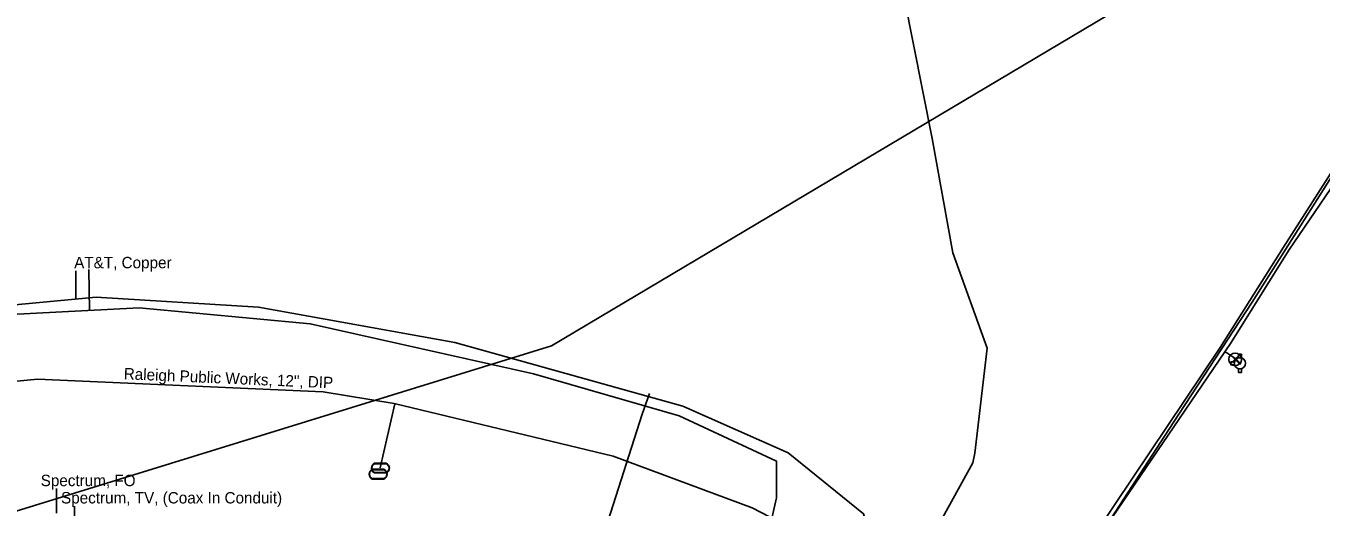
# Model space of a CAD drawing. Extents: x 2070721 to 2083340, y 729290 to 737883.
# Drawn here: x 2081646.1 to 2082100.6, y 734963.1 to 735132 of the extents above; entities that cross this region are included whole.
import ezdxf

# ---------------------------------------------------------------- set-up
doc = ezdxf.new("R2010")
doc.units = 0
for name, color, linetype in [('Exist Utilities Other Unknown UG SUE LOS B', 7, 'Continuous'), ('Exist Utilities Power UG Cable SUE LOS C', 7, 'Continuous'), ('Exist Utilities Telephone UG Cable SUE LOS C', 7, 'Continuous'), ('Exist Utilities Telephone UG Cable SUE LOS C Leader', 7, 'Continuous'), ('Exist Utilities Telephone UG Cable SUE LOS C Text', 7, 'Continuous'), ('Exist Utilities Telephone UG Conduit SUE LOS B', 7, 'Continuous'), ('Exist Utilities TV UG Cable SUE LOS B Leader', 7, 'Continuous'), ('Exist Utilities TV UG Cable SUE LOS B Text', 7, 'Continuous'), ('Exist Utilities TV UG FO Cable SUE LOS B Leader', 7, 'Continuous'), ('Exist Utilities TV UG FO Cable SUE LOS B Text', 7, 'Continuous'), ('Exist Utilities Water Fire Hydrant CELL', 7, 'Continuous'), ('Exist Utilities Water Meter CELL', 7, 'Continuous'), ('Exist Utilities Water UG Line SUE LOS B', 7, 'Continuous'), ('Exist Utilities Water UG Line SUE LOS B Text', 7, 'Continuous'), ('Exist Utilities Water Valve CELL', 7, 'Continuous')]:
    doc.layers.add(name, color=color, linetype=linetype)

msp = doc.modelspace()

# ---------------------------------------------------------------- linework, layer by layer
at = {"layer": 'Exist Utilities Other Unknown UG SUE LOS B'}
for points in [[(2081978.43, 734978.59), (2081979.11, 734982), (2081983.42, 735018.9), (2081971.42, 735052.39), (2081964.16, 735092.46), (2081954.33, 735142.07), (2081952.63, 735178.63), (2081957.65, 735210.93), (2081969.83, 735251.04)], [(2081599.02, 734480.52), (2081638.91, 734537.92), (2081689.31, 734601.45), (2081739.23, 734661.21), (2081776.34, 734700.28), (2081815.77, 734743.2), (2081849.28, 734780.93), (2081877.42, 734814.37), (2081912.75, 734856.19), (2081950.81, 734928.53), (2081978.43, 734978.59)]]:
    msp.add_lwpolyline(points, dxfattribs=at)
at = {"layer": 'Exist Utilities Power UG Cable SUE LOS C'}
for points in [[(2080186.05, 734475.29), (2080187.03, 734475.63), (2080448.94, 734565.1), (2080663.08, 734641.37), (2080827.26, 734699.95), (2080984.4, 734756.05), (2081109.44, 734801.16), (2081210.88, 734831.9), (2081586.98, 734944.46), (2081830.55, 735019.69), (2082038.54, 735143.44), (2082248.34, 735270.09)], [(2081398.46, 734886.3), (2081460.49, 734911.77), (2081509.14, 734930.55), (2081563.83, 734950.54), (2081592.79, 734954.64), (2081621.06, 734958.42), (2081630.74, 734957.65), (2081639.48, 734957.65), (2081657.7, 734957.65), (2081672.52, 734956.07), (2081771.45, 734941.91), (2081817.43, 734931.74), (2081831.08, 734932.73), (2081838.68, 734936.87), (2081850.29, 734958.08), (2081862.4, 734995.7), (2081864.93, 735002.95)]]:
    msp.add_lwpolyline(points, dxfattribs=at)
at = {"layer": 'Exist Utilities Telephone UG Cable SUE LOS C'}
for points in [[(2080527.18, 734594.58), (2080756.63, 734677.7), (2080975.53, 734755.33), (2081114.85, 734806.49), (2081251.31, 734880.3), (2081357.91, 734934.96), (2081407.46, 734955.63), (2081557.34, 735013.56), (2081611.19, 735031.21), (2081670.8, 735036.79), (2081727.82, 735033.26), (2081796.62, 735020.83), (2081876.61, 734998.57), (2081913.61, 734982.12), (2081940.08, 734960.79), (2081955.36, 734908.6), (2081940.34, 734844.38), (2081917.15, 734795.51)], [(2080934.26, 734720.97), (2081041, 734761.39), (2081061.56, 734773.15), (2081150.65, 734813.71), (2081201.33, 734846.96), (2081300.64, 734903.05), (2081400.2, 734948.86), (2081476.71, 734979.23), (2081590.79, 735021.91), (2081620.53, 735029.68), (2081685.91, 735033.08), (2081745.92, 735027.46), (2081824.22, 735009.88), (2081875.43, 734995.15), (2081909.49, 734979.28), (2081909.49, 734966.35), (2081906.46, 734953.04)]]:
    msp.add_lwpolyline(points, dxfattribs=at)
at = {"layer": 'Exist Utilities Telephone UG Cable SUE LOS C Leader'}
for p, q in [((2081663.66, 735036.11), (2081663.66, 735046.07)), ((2081668.46, 735032.23), (2081668.2, 735046.43))]:
    msp.add_line(p, q, dxfattribs=at)
at = {"layer": 'Exist Utilities Telephone UG Conduit SUE LOS B'}
for points in [[(2081917.15, 734795.51), (2082009.52, 734932.29), (2082048.72, 734992.73), (2082076.42, 735035.03), (2082121.27, 735105.83), (2082143.4, 735134.38), (2082165.12, 735153.55), (2082206.17, 735181.11), (2082253.91, 735195.11), (2082261.15, 735199.69), (2082263.21, 735230.16), (2082267.94, 735269.33), (2082270.97, 735300.6), (2082279.44, 735366.27), (2082282.16, 735384.08), (2082312.89, 735448.88), (2082332.37, 735470.01), (2082345.07, 735482.69), (2082399.03, 735538.34), (2082399, 735549.46), (2082395.14, 735556.12)], [(2082022.07, 734954.73), (2082065.19, 735019.13), (2082087.45, 735054.31), (2082120.86, 735106.65)]]:
    msp.add_lwpolyline(points, dxfattribs=at)
at = {"layer": 'Exist Utilities TV UG Cable SUE LOS B Leader'}
msp.add_line((2081663.14, 734959.52), (2081663.14, 734963.39), dxfattribs=at)
at = {"layer": 'Exist Utilities TV UG FO Cable SUE LOS B Leader'}
msp.add_line((2081656.86, 734960.96), (2081656.86, 734969.6), dxfattribs=at)
at = {"layer": 'Exist Utilities Water Fire Hydrant CELL'}
msp.add_line((2082072.13, 735013.56), (2082072.13, 735013.56), dxfattribs=at)
for points in [[(2082071.61, 735015.47), (2082071.61, 735016.76), (2082072.64, 735016.76), (2082072.64, 735015.45)], [(2082070.21, 735014.07), (2082068.93, 735014.07), (2082068.93, 735013.05), (2082070.21, 735013.05)], [(2082071.61, 735011.65), (2082071.61, 735010.36), (2082072.64, 735010.36), (2082072.64, 735011.67)]]:
    msp.add_lwpolyline(points, dxfattribs=at)
for radius in [1.98, 0.243]:
    msp.add_circle((2082072.13, 735013.56), radius, dxfattribs=at)
at = {"layer": 'Exist Utilities Water Meter CELL'}
for p, q in [((2081769.76, 734974.66), (2081769.76, 734974.66)), ((2081770.56, 734976.78), (2081770.56, 734976.78))]:
    msp.add_line(p, q, dxfattribs=at)
for points in [[(2081768.52, 734978.48), (2081772.6, 734978.48)], [(2081768.52, 734978.34), (2081772.6, 734978.34)], [(2081767.72, 734976.36), (2081771.8, 734976.36)], [(2081767.72, 734976.22), (2081771.8, 734976.22)], [(2081772.6, 734975.22), (2081768.5, 734975.22)], [(2081772.6, 734975.08), (2081768.5, 734975.08)], [(2081771.8, 734973.1), (2081767.7, 734973.1)], [(2081771.8, 734972.96), (2081767.7, 734972.96)]]:
    msp.add_lwpolyline(points, dxfattribs=at)
for centre, radius, start, end in [((2081769.25, 734976.77), 1.86, 113.178, 245.9794), ((2081769.26, 734976.77), 1.73, 115.3009, 243.7824), ((2081771.85, 734976.78), 1.86, 293.6483, 66.3084), ((2081771.86, 734976.78), 1.73, 295.1272, 64.8728), ((2081768.45, 734974.65), 1.86, 113.178, 245.9794), ((2081768.46, 734974.65), 1.73, 115.3009, 243.7824), ((2081771.05, 734974.66), 1.86, 293.6483, 66.3084), ((2081771.06, 734974.66), 1.73, 295.1272, 64.8728)]:
    msp.add_arc(centre, radius, start, end, dxfattribs=at)
at = {"layer": 'Exist Utilities Water UG Line SUE LOS B'}
for p, q in [((2082066.86, 735017.58), (2082023.39, 734953.58)), ((2081770.42, 734976.9), (2081775.58, 734999.35))]:
    msp.add_line(p, q, dxfattribs=at)
for points in [[(2082136.84, 735123.04), (2082089.32, 735053.22), (2082069.05, 735020.82), (2082066.86, 735017.58), (2082066.86, 735017.58), (2082066.86, 735017.58)], [(2082066.86, 735017.58), (2082067.6, 735017.21), (2082070.69, 735015.09), (2082072.21, 735013.65)], [(2080902.52, 734692.58), (2081024.44, 734735.33), (2081064.65, 734749.07), (2081167.38, 734801.25), (2081288.56, 734870.47), (2081329.8, 734893.5), (2081435.94, 734938.99), (2081596, 735000.71), (2081611.53, 735004.3), (2081650.19, 735007.99), (2081750.43, 735003.6), (2081775.33, 734999.48), (2081852.16, 734980.94), (2081900.97, 734962.81), (2081973.29, 734925.34), (2081993.87, 734913.23), (2081994.94, 734912.69)]]:
    msp.add_lwpolyline(points, dxfattribs=at)
at = {"layer": 'Exist Utilities Water Valve CELL'}
msp.add_lwpolyline([(2082072.04, 735016.51), (2082068.89, 735013.36), (2082070.47, 735014.94), (2082072.04, 735013.36), (2082068.89, 735016.51)], dxfattribs=at)
msp.add_circle((2082070.47, 735014.94), 2.23, dxfattribs=at)

# ---------------------------------------------------------------- texts
at = {"layer": 'Exist Utilities Telephone UG Cable SUE LOS C Text'}
msp.add_text('AT&T, Copper', height=4, dxfattribs=at).set_placement((2081663.08, 735046.92))
at = {"layer": 'Exist Utilities TV UG Cable SUE LOS B Text'}
msp.add_text('Spectrum, TV, (Coax In Conduit)', height=4, dxfattribs=at).set_placement((2081658.47, 734964.38))
at = {"layer": 'Exist Utilities TV UG FO Cable SUE LOS B Text'}
msp.add_text('Spectrum, FO', height=4, dxfattribs=at).set_placement((2081651.33, 734970.45))
at = {"layer": 'Exist Utilities Water UG Line SUE LOS B Text'}
msp.add_text('Raleigh Public Works, 12", DIP ', height=4, rotation=357.4923, dxfattribs=at).set_placement((2081680.41, 735007.98))

doc.saveas('drawing.dxf')
